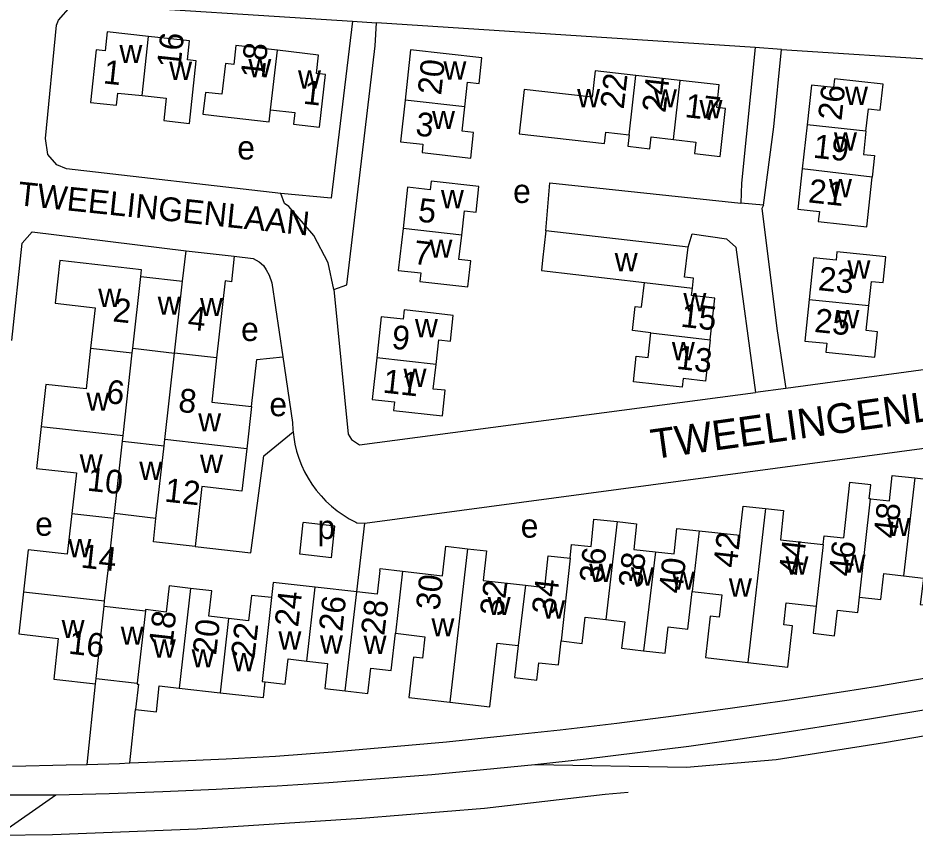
# Model space of a CAD drawing. Extents: x 161936 to 163647, y 386450 to 388633.
# Drawn here: x 162656.6 to 162807.7, y 386455.4 to 386593 of the extents above; entities that cross this region are included whole.
import ezdxf

# ---------------------------------------------------------------- set-up
doc = ezdxf.new("R2010")
doc.units = 0
for name, color, linetype in [('BLT_Basislijn', 7, 'Continuous'), ('BLT_Bebouwing', 7, 'Continuous'), ('BLT_Centroide', 7, 'Continuous'), ('BLT_Huisnummer', 7, 'Continuous'), ('BLT_Huisnummer_ tussenligend', 7, 'Continuous'), ('BLT_Huisnummer_reeks', 7, 'Continuous'), ('BLT_Onderdoorgang_en_onderverdeling', 7, 'Continuous'), ('BLT_Onderverdeling_panden', 7, 'Continuous'), ('BLT_Straatnaam', 7, 'Continuous'), ('BLT_Straatnaam_verkleind', 7, 'Continuous'), ('BLT_Vlakafsluiter', 7, 'Continuous')]:
    doc.layers.add(name, color=color, linetype=linetype)

msp = doc.modelspace()

# ---------------------------------------------------------------- linework, layer by layer
at = {"layer": 'BLT_Basislijn'}
for p, q in [((162713.01, 386592.44), (162717.03, 386592.2)), ((162780.78, 386588), (162717.03, 386592.2)), ((162785.23, 386587.71), (162780.78, 386588)), ((162782.18, 386561.46), (162778.41, 386561.84)), ((162659.05, 386557), (162684.99, 386553.82)), ((162699.39, 386548.43), (162701.24, 386535.97)), ((162701.24, 386535.97), (162702.89, 386524.91)), ((162785.97, 386530.63), (162780.83, 386529.95)), ((162704.1, 386502.73), (162704.65, 386508.03)), ((162709.43, 386502.12), (162709.99, 386507.42)), ((162713.69, 386496.39), (162715.08, 386507.97)), ((162800.38, 386475.05), (162903.47, 386492.41)), ((162668.3, 386467.34), (162669.7, 386480.91)), ((162675.51, 386467.57), (162676.46, 386476.6))]:
    msp.add_line(p, q, dxfattribs=at)
for points in [[(162700.89, 386563.47), (162664.84, 386567.62), (162663.18, 386568.3), (162661.66, 386570.04), (162661.31, 386572.71), (162663.15, 386591.79), (162663.47, 386592.62), (162665.57, 386594.96), (162667.26, 386595.36), (162713.01, 386592.44)], [(162713.01, 386592.44), (162709.37, 386562.66), (162700.89, 386563.47)], [(162709.82, 386547.31), (162712.04, 386548.09), (162716.8, 386588.3), (162717.03, 386592.2)], [(162780.78, 386588), (162778.51, 386565.16), (162778.41, 386561.84)], [(162782.18, 386561.46), (162783.92, 386574.65), (162785.23, 386587.71)], [(162785.23, 386587.71), (162841.02, 386584.11), (162844.62, 386583.54), (162846.79, 386581.59), (162847.4, 386578.61), (162842.61, 386541.25), (162842.22, 386540.22), (162841.29, 386538.99), (162838.89, 386537.8), (162785.97, 386530.63)], [(162745.56, 386557.18), (162746.19, 386565.25), (162778.41, 386561.84)], [(162709.82, 386547.31), (162708.86, 386551.75), (162706.47, 386556.37), (162702.27, 386561.24), (162701.53, 386561.74), (162700.89, 386563.47)], [(162782.18, 386561.46), (162781.94, 386560.94), (162784.48, 386540.33), (162785.97, 386530.63)], [(162655.59, 386538.71), (162657.34, 386555.09), (162659.05, 386557)], [(162769.5, 386554.43), (162770.2, 386556.64), (162775.96, 386555.82), (162777.55, 386554.39), (162780.83, 386529.95)], [(162693.07, 386552.89), (162696.28, 386552.48), (162697.29, 386551.96), (162697.98, 386551.33), (162698.47, 386550.6), (162698.93, 386549.67), (162699.39, 386548.43)], [(162709.82, 386547.31), (162712.28, 386522.91), (162712.81, 386522.01), (162714.18, 386521.12), (162780.83, 386529.95)], [(162695.96, 386527.58), (162696.89, 386535.5), (162701.24, 386535.97)], [(162715.08, 386507.97), (162847.81, 386525.76)], [(162702.89, 386524.91), (162702.94, 386523.68), (162702.98, 386523.3)], [(162686.48, 386504.04), (162695.89, 386502.94), (162698.03, 386519.27), (162702.98, 386523.3)], [(162702.98, 386523.3), (162703.08, 386522.45), (162703.29, 386521.24), (162703.58, 386520.05), (162703.95, 386518.87), (162704.4, 386517.72), (162704.92, 386516.61), (162705.51, 386515.53), (162706.16, 386514.49), (162706.89, 386513.49), (162707.68, 386512.55), (162708.52, 386511.65), (162709.43, 386510.82), (162710.39, 386510.04), (162711.39, 386509.33), (162712.44, 386508.69), (162713.53, 386508.11), (162713.71, 386508.02), (162715.08, 386507.97)], [(162709.99, 386507.42), (162704.65, 386508.03)], [(162709.43, 386502.12), (162704.1, 386502.73)], [(162801.42, 386480.49), (162886.01, 386494.96), (162889.55, 386495.55)], [(162743.7, 386467.33), (162769.26, 386466.87), (162784.31, 386468.15), (162802.58, 386471.04), (162904.51, 386488.39)], [(162699.99, 386468.74), (162709.6, 386469.47), (162719.2, 386470.27), (162728.79, 386471.16), (162738.37, 386472.12), (162747.95, 386473.17), (162757.51, 386474.29), (162767.07, 386475.49), (162776.61, 386476.78), (162786.15, 386478.14), (162795.67, 386479.58), (162801.42, 386480.49)], [(162743.7, 386467.33), (162752.35, 386468.28), (162761, 386469.32), (162769.64, 386470.43), (162778.27, 386471.62), (162786.89, 386472.9), (162795.49, 386474.25), (162800.38, 386475.05)], [(162675.51, 386467.57), (162682.72, 386467.85), (162691.71, 386468.28), (162699.99, 386468.74)], [(162655.74, 386467.05), (162664.74, 386467.24), (162668.3, 386467.34)], [(162668.3, 386467.34), (162673.73, 386467.5), (162675.51, 386467.57)], [(162700.29, 386463.75), (162708.99, 386464.31), (162717.67, 386464.94), (162726.36, 386465.66), (162735.03, 386466.45), (162743.7, 386467.33)], [(162569.36, 386464.86), (162634.81, 386462.19), (162663, 386462.19)], [(162663, 386462.19), (162672.02, 386462.44), (162681.04, 386462.78), (162690.05, 386463.18), (162699.06, 386463.68), (162700.29, 386463.75)], [(162653.28, 386455.44), (162662.47, 386455.54), (162686.82, 386456.47), (162714.52, 386458.26), (162735.24, 386459.99), (162755.52, 386462.32), (162759.42, 386462.66)]]:
    msp.add_lwpolyline(points, dxfattribs=at)
at = {"layer": 'BLT_Bebouwing'}
for p, q in [((162768.18, 386582.47), (162760.68, 386583.32)), ((162789.53, 386575.01), (162788.72, 386567.61)), ((162769.5, 386554.43), (162745.56, 386557.18)), ((162684.36, 386548.67), (162684.99, 386553.82)), ((162684.99, 386553.82), (162693.07, 386552.89)), ((162677.32, 386549.5), (162677.44, 386550.62)), ((162677.32, 386549.5), (162684.36, 386548.67)), ((162675.88, 386536.6), (162675.97, 386537.38)), ((162675.97, 386537.38), (162683.01, 386536.57)), ((162674.34, 386522.69), (162675.88, 386536.6)), ((162681.38, 386522.02), (162683.01, 386536.57)), ((162695.96, 386527.58), (162695.17, 386520.47)), ((162674.23, 386521.74), (162674.34, 386522.69)), ((162674.23, 386521.74), (162681.26, 386520.94)), ((162681.26, 386520.94), (162681.38, 386522.02)), ((162671.82, 386500), (162672.79, 386508.78)), ((162672.79, 386508.78), (162672.88, 386509.6)), ((162679.89, 386508.71), (162672.88, 386509.6)), ((162658.34, 386503.47), (162657.56, 386496.38)), ((162671.24, 386494.86), (162671.82, 386500)), ((162713.69, 386496.39), (162706.71, 386497.18)), ((162671.15, 386493.95), (162671.24, 386494.86)), ((162669.7, 386480.91), (162669.79, 386481.77)), ((162669.79, 386481.77), (162676.72, 386481)), ((162683.78, 386480.19), (162690.7, 386479.4))]:
    msp.add_line(p, q, dxfattribs=at)
for points in [[(162678.61, 386589.9), (162671.65, 386590.65), (162671.31, 386587.48), (162669.81, 386587.64), (162668.86, 386578.79), (162673.23, 386578.32), (162673.45, 386580.36), (162677.54, 386579.92)], [(162677.54, 386579.92), (162681.63, 386579.49), (162681.23, 386575.71), (162685.54, 386575.24), (162686.67, 386585.81), (162685.21, 386585.96), (162685.55, 386589.16), (162678.61, 386589.9)], [(162700.33, 386587.55), (162693.36, 386588.34), (162693, 386585.17), (162691.58, 386585.33), (162690.99, 386580.16), (162688.21, 386580.47), (162687.8, 386576.79), (162690.58, 386576.47), (162698.97, 386575.53), (162699.2, 386577.53)], [(162699.2, 386577.53), (162703.29, 386577.07), (162703.07, 386575.12), (162707.43, 386574.63), (162708.43, 386583.46), (162706.93, 386583.63), (162707.28, 386586.76), (162700.33, 386587.55)], [(162731.89, 386578.06), (162732.35, 386582.18), (162734.31, 386581.97), (162734.79, 386586.28), (162722.76, 386587.61), (162721.83, 386579.17)], [(162760.68, 386583.32), (162753.87, 386584.09), (162753.36, 386579.66), (162741.89, 386580.96), (162741.04, 386573.47), (162755.4, 386571.84), (162755.62, 386573.78), (162759.55, 386573.33)], [(162799.45, 386573.93), (162799.87, 386577.71), (162801.87, 386577.49), (162802.34, 386581.85), (162794.17, 386582.74), (162794.01, 386581.31), (162790.26, 386581.71), (162789.53, 386575.01)], [(162767.05, 386572.53), (162770.81, 386572.11), (162770.6, 386570.19), (162774.88, 386569.7), (162775.8, 386577.78), (162774.32, 386577.95), (162774.74, 386581.72), (162768.18, 386582.47)], [(162721.83, 386579.17), (162721.05, 386572.15), (162724.84, 386571.73), (162724.69, 386570.33), (162732.9, 386569.42), (162733.37, 386573.72), (162731.43, 386573.93), (162731.89, 386578.06)], [(162799.45, 386573.93), (162799.03, 386570.02), (162800.88, 386569.82), (162800.49, 386566.22)], [(162759.55, 386573.33), (162759.33, 386571.42), (162763.07, 386570.99), (162763.29, 386572.96), (162767.05, 386572.53)], [(162788.72, 386567.61), (162787.98, 386560.82), (162791.61, 386560.43), (162791.43, 386558.72), (162799.58, 386557.83), (162800.49, 386566.22)], [(162731.37, 386556.42), (162731.83, 386560.53), (162733.8, 386560.31), (162734.28, 386564.63), (162726.21, 386565.53), (162726.04, 386564.07), (162722.27, 386564.49), (162721.49, 386557.53)], [(162721.49, 386557.53), (162720.7, 386550.49), (162724.48, 386550.07), (162724.32, 386548.65), (162732.41, 386547.74), (162732.89, 386552.09), (162730.91, 386552.31), (162731.37, 386556.42)], [(162745.56, 386557.18), (162744.99, 386552.22), (162744.79, 386550.46), (162762.15, 386548.46)], [(162770.24, 386547.53), (162770.43, 386549.19), (162768.91, 386549.36), (162769.5, 386554.43)], [(162693.07, 386552.89), (162692.59, 386548.6), (162691.55, 386548.72), (162690.1, 386535.76)], [(162799.94, 386544.58), (162800.37, 386548.65), (162802.34, 386548.45), (162802.79, 386552.8), (162799.55, 386553.14), (162794.57, 386553.65), (162794.42, 386552.22), (162790.62, 386552.62), (162789.9, 386545.61)], [(162677.44, 386550.62), (162663.7, 386552.15), (162662.9, 386544.96), (162669.63, 386544.22), (162668.87, 386537.38)], [(162763.23, 386540.01), (162760.13, 386540.37), (162760.59, 386544.42), (162761.67, 386544.3), (162762.15, 386548.46)], [(162773.22, 386538.79), (162774.03, 386545.84), (162770.1, 386546.29), (162770.24, 386547.53)], [(162789.9, 386545.61), (162789.17, 386538.61), (162792.87, 386538.23), (162792.71, 386536.75), (162800.95, 386535.9), (162801.39, 386540.18), (162799.51, 386540.38), (162799.94, 386544.58)], [(162727.05, 386534.67), (162727.51, 386538.81), (162729.47, 386538.6), (162729.95, 386542.93), (162726.65, 386543.3), (162721.68, 386543.85), (162721.51, 386542.27), (162717.83, 386542.68), (162717.07, 386535.77)], [(162773.22, 386538.79), (162772.43, 386531.88), (162768.67, 386532.31), (162768.49, 386530.82), (162760.29, 386531.76), (162760.78, 386536.05), (162762.75, 386535.83), (162763.23, 386540.01)], [(162668.87, 386537.38), (162668.11, 386530.54), (162661.34, 386531.29), (162660.56, 386524.22)], [(162690.1, 386535.76), (162689.27, 386528.33), (162695.96, 386527.58)], [(162717.07, 386535.77), (162716.3, 386528.79), (162720.03, 386528.38), (162719.87, 386526.92), (162728.12, 386526.01), (162728.6, 386530.31), (162726.59, 386530.53), (162727.05, 386534.67)], [(162660.56, 386524.22), (162659.77, 386517.15), (162666.48, 386516.4), (162665.72, 386509.57)], [(162695.17, 386520.47), (162694.37, 386513.36), (162687.61, 386514.12), (162686.48, 386504.04)], [(162800.2, 386512.02), (162799.99, 386512.05), (162800.25, 386514.41), (162796.66, 386514.79), (162795.65, 386505.48)], [(162800.2, 386512.02), (162803.42, 386511.68), (162803.88, 386515.96), (162807.67, 386515.55)], [(162807.67, 386515.55), (162810.97, 386515.2), (162810.5, 386510.82), (162814.15, 386510.43)], [(162771.36, 386506.66), (162778.23, 386505.92), (162778.76, 386510.81), (162782.54, 386510.4)], [(162782.54, 386510.4), (162785.58, 386510.07), (162785.05, 386505.15), (162792.24, 386504.38)], [(162665.72, 386509.57), (162664.96, 386502.73), (162658.34, 386503.47)], [(162686.48, 386504.04), (162679.45, 386504.83), (162679.89, 386508.71)], [(162749.63, 386502.07), (162749.88, 386504.37), (162753.15, 386504.01), (162753.65, 386508.64), (162757.53, 386508.22)], [(162757.53, 386508.21), (162760.82, 386507.86), (162760.35, 386503.51), (162764.03, 386503.12)], [(162764.03, 386503.12), (162767.14, 386502.78), (162767.6, 386507.07), (162771.36, 386506.66)], [(162792.24, 386504.38), (162792.4, 386505.82), (162795.65, 386505.48)], [(162728.12, 386499.09), (162728.69, 386504.05), (162732.33, 386503.64)], [(162732.33, 386503.64), (162735.57, 386503.26), (162735, 386498.3), (162742.13, 386497.48)], [(162742.13, 386497.48), (162745.37, 386497.14), (162745.94, 386502.46), (162749.63, 386502.07)], [(162717.6, 386500), (162717.14, 386495.99), (162713.69, 386496.39)], [(162717.6, 386500), (162717.63, 386500.29), (162721.42, 386499.86)], [(162721.42, 386499.86), (162728.12, 386499.09)], [(162798.36, 386495.51), (162801.97, 386495.1), (162802.46, 386499.45), (162805.78, 386499.07)], [(162706.71, 386497.18), (162699.64, 386497.98), (162699.34, 386495.41)], [(162805.78, 386499.07), (162809.12, 386498.68), (162808.61, 386494.27), (162812.25, 386493.86)], [(162685.7, 386496.97), (162682.12, 386497.38), (162681.62, 386492.99), (162678.14, 386493.39), (162678.11, 386493.17)], [(162692.13, 386491.88), (162688.79, 386492.27), (162689.28, 386496.56), (162685.7, 386496.97)], [(162761.97, 386486.46), (162765.64, 386486.04), (162766.15, 386490.49), (162769.46, 386490.11), (162770.19, 386496.43)], [(162770.19, 386496.43), (162775.16, 386495.86), (162774.73, 386492.1), (162773.24, 386492.27), (162772.44, 386485.31), (162779.57, 386484.49)], [(162657.56, 386496.38), (162656.77, 386489.29), (162663.43, 386488.55), (162662.66, 386481.69), (162669.7, 386480.91)], [(162699.34, 386495.41), (162695.96, 386495.79), (162695.47, 386491.5), (162692.13, 386491.88)], [(162791.06, 386493.97), (162790.54, 386489.41), (162794.18, 386489), (162794.67, 386493.3), (162798.07, 386492.92), (162798.36, 386495.51)], [(162671.15, 386493.95), (162678.11, 386493.17)], [(162779.57, 386484.49), (162786.28, 386483.72), (162787.08, 386490.67), (162785.61, 386490.84), (162786.04, 386494.55), (162791.06, 386493.97)], [(162748.15, 386488.11), (162751.66, 386487.71), (162752.17, 386492.12), (162755.65, 386491.72)], [(162755.65, 386491.72), (162758.82, 386491.36), (162758.3, 386486.88), (162761.97, 386486.46)], [(162711.75, 386479.73), (162715.57, 386479.29), (162716.06, 386483.55), (162719.5, 386483.16), (162720.21, 386489.4)], [(162720.21, 386489.4), (162725.18, 386488.83), (162724.76, 386485.21), (162723.23, 386485.38), (162722.46, 386478.59), (162729.37, 386477.79)], [(162729.37, 386477.79), (162736.14, 386477.02), (162737.37, 386487.76), (162740.86, 386487.36)], [(162740.86, 386487.36), (162740.24, 386481.97), (162744, 386481.53), (162744.34, 386484.46), (162747.69, 386484.08), (162748.15, 386488.11)], [(162698.28, 386481.22), (162701.66, 386480.83), (162702.15, 386485.09), (162705.27, 386484.73)], [(162705.27, 386484.73), (162708.8, 386484.32), (162708.32, 386480.12), (162711.75, 386479.73)], [(162676.72, 386481), (162676.7, 386480.85), (162676.94, 386480.82), (162676.46, 386476.6)], [(162676.46, 386476.6), (162679.95, 386476.2), (162680.45, 386480.58), (162683.78, 386480.19)], [(162690.7, 386479.4), (162697.98, 386478.57), (162698.28, 386481.22)]]:
    msp.add_lwpolyline(points, dxfattribs=at)
at = {"layer": 'BLT_Onderdoorgang_en_onderverdeling'}
for p, q in [((162675.97, 386537.38), (162677.32, 386549.5)), ((162683.01, 386536.57), (162684.36, 386548.67)), ((162672.88, 386509.6), (162674.23, 386521.74)), ((162679.89, 386508.71), (162681.26, 386520.94)), ((162669.79, 386481.77), (162671.15, 386493.95)), ((162678.11, 386493.17), (162676.72, 386481))]:
    msp.add_line(p, q, dxfattribs=at)
at = {"layer": 'BLT_Onderverdeling_panden'}
for p, q in [((162677.54, 386579.92), (162678.61, 386589.9)), ((162699.2, 386577.53), (162700.33, 386587.55)), ((162759.55, 386573.33), (162760.68, 386583.32)), ((162767.05, 386572.53), (162768.18, 386582.47)), ((162731.89, 386578.06), (162721.83, 386579.17)), ((162799.45, 386573.93), (162789.53, 386575.01)), ((162800.49, 386566.22), (162788.72, 386567.61)), ((162731.37, 386556.42), (162721.49, 386557.53)), ((162762.15, 386548.46), (162770.24, 386547.53)), ((162789.9, 386545.61), (162799.94, 386544.58)), ((162763.23, 386540.01), (162773.22, 386538.79)), ((162668.87, 386537.38), (162675.88, 386536.6)), ((162690.1, 386535.76), (162683.01, 386536.57)), ((162727.05, 386534.67), (162717.07, 386535.77)), ((162660.56, 386524.22), (162674.34, 386522.69)), ((162695.17, 386520.47), (162681.38, 386522.02)), ((162807.67, 386515.55), (162805.78, 386499.07)), ((162798.36, 386495.51), (162800.2, 386512.02)), ((162782.54, 386510.4), (162779.57, 386484.49)), ((162665.72, 386509.57), (162672.79, 386508.78)), ((162757.53, 386508.22), (162755.65, 386491.72)), ((162771.36, 386506.66), (162770.19, 386496.43)), ((162792.24, 386504.38), (162791.06, 386493.97)), ((162732.33, 386503.64), (162729.37, 386477.79)), ((162764.03, 386503.12), (162761.97, 386486.46)), ((162749.63, 386502.07), (162748.15, 386488.11)), ((162721.42, 386499.86), (162720.21, 386489.4)), ((162685.7, 386496.97), (162683.78, 386480.19)), ((162705.27, 386484.73), (162706.71, 386497.18)), ((162742.13, 386497.48), (162740.86, 386487.36)), ((162657.56, 386496.38), (162671.24, 386494.86)), ((162711.75, 386479.73), (162713.69, 386496.39)), ((162692.13, 386491.88), (162690.7, 386479.4))]:
    msp.add_line(p, q, dxfattribs=at)
msp.add_lwpolyline([(162699.34, 386495.41), (162697.77, 386481.28), (162698.28, 386481.22)], dxfattribs=at)
at = {"layer": 'BLT_Vlakafsluiter'}
msp.add_line((162653.28, 386455.44), (162663, 386462.19), dxfattribs=at)

# ---------------------------------------------------------------- texts
at = {"layer": 'BLT_Centroide'}
for s, p in [('w', (162673.73, 386585.39)), ('w', (162682.11, 386582.58)), ('w', (162695.45, 386583.03)), ('w', (162728.3, 386582.62)), ('w', (162703.81, 386581.09)), ('w', (162750.81, 386577.97)), ('w', (162763.75, 386577.94)), ('w', (162795.92, 386578.34)), ('w', (162771.42, 386576.09)), ('w', (162726.38, 386574.28)), ('w', (162794.07, 386570.66)), ('e', (162693.58, 386569.17)), ('e', (162740.03, 386561.85)), ('w', (162793.23, 386562.81)), ('w', (162727.88, 386560.97)), ('w', (162725.95, 386552.62)), ('w', (162757.14, 386550.34)), ('w', (162796.34, 386549.12)), ('w', (162670.17, 386544.33)), ('w', (162768.71, 386543.62)), ('w', (162680.17, 386543.03)), ('w', (162687.3, 386542.8)), ('w', (162794.47, 386540.75)), ('e', (162694.22, 386538.61)), ('w', (162723.5, 386539.25)), ('w', (162766.77, 386535.38)), ('w', (162721.58, 386530.88)), ('w', (162668.18, 386526.86)), ('e', (162698.99, 386525.95)), ('w', (162687, 386523.39)), ('w', (162667.05, 386516.45)), ('w', (162687.31, 386516.38)), ('w', (162677.08, 386515.23)), ('e', (162659.54, 386505.82)), ('e', (162741.31, 386505.5)), ('w', (162803.05, 386505.77)), ('p', (162707.09, 386505.28)), ('w', (162665.13, 386502.22)), ('w', (162795.53, 386499.59)), ('w', (162752.86, 386498.03)), ('w', (162785.91, 386499.3)), ('w', (162759.88, 386497.44)), ('w', (162766.77, 386496.73)), ('w', (162776.38, 386495.56)), ('w', (162735.75, 386492.47)), ('w', (162744.92, 386491.88)), ('w', (162726.28, 386488.88)), ('w', (162664, 386488.59)), ('w', (162673.95, 386487.47)), ('w', (162700.51, 386486.66)), ('w', (162707.5, 386485.98)), ('w', (162714.85, 386485.92)), ('w', (162679.36, 386485.3)), ('w', (162685.88, 386483.66)), ('w', (162692.75, 386483.01))]:
    msp.add_text(s, height=4, dxfattribs=at).set_placement(p)
at = {"layer": 'BLT_Huisnummer'}
for s, rotation, p in [('16', 83.8872, (162684, 386584.41)), ('18', 83.5588, (162698.09, 386582.69)), ('1', 353.8873, (162670.9, 386582)), ('20', 83.6728, (162727.9, 386579.9)), ('22', 83.5207, (162758.65, 386577.55)), ('24', 83.5155, (162765.69, 386576.93)), ('1', 353.5603, (162704.57, 386578.58)), ('26', 83.8011, (162795.33, 386575.62)), ('17', 353.5028, (162768.83, 386576.32)), ('3', 353.6751, (162723.49, 386573.23)), ('19', 353.7932, (162790.45, 386569.49)), ('21', 353.7889, (162789.63, 386561.97)), ('5', 353.6108, (162723.89, 386558.74)), ('7', 353.6194, (162723.12, 386551.61)), ('23', 354.102, (162791.29, 386547.19)), ('15', 353.4398, (162768.14, 386541.04)), ('25', 354.0979, (162790.66, 386540.15)), ('9', 353.7001, (162719.45, 386537.36)), ('13', 353.4422, (162767.41, 386533.94)), ('11', 353.6956, (162717.98, 386529.94)), ('6', 353.6566, (162671.39, 386528.18)), ('8', 353.6108, (162683.53, 386526.72)), ('42', 83.4655, (162777.69, 386500.32)), ('14', 353.6598, (162667.12, 386500.49)), ('46', 83.6454, (162797.13, 386498.86)), ('38', 83.47, (162761.71, 386496.91)), ('30', 83.9216, (162727.62, 386493.18)), ('34', 83.47, (162747.12, 386492.42)), ('26', 83.4717, (162711.26, 386489.58)), ('22', 83.4629, (162696.46, 386485.04))]:
    msp.add_text(s, height=4, rotation=rotation, dxfattribs=at).set_placement(p)
at = {"layer": 'BLT_Huisnummer_ tussenligend'}
for s, rotation, p in [('48', 83.4676, (162804.66, 386505.26)), ('44', 83.5555, (162788.71, 386499.01)), ('36', 83.9216, (162755.14, 386497.76)), ('40', 83.4658, (162768.5, 386495.99)), ('32', 82.8413, (162738.36, 386492.16)), ('24', 83.4703, (162703.82, 386490.36)), ('28', 82.8413, (162718.32, 386488.92)), ('20', 83.4684, (162690.01, 386485.64))]:
    msp.add_text(s, height=4, rotation=rotation, dxfattribs=at).set_placement(p)
at = {"layer": 'BLT_Huisnummer_reeks'}
for s, rotation, p in [('2', 353.6625, (162672.5, 386541.93)), ('4', 353.4895, (162685.1, 386540.59)), ('10', 353.6634, (162668.18, 386513.44)), ('12', 353.6115, (162681.2, 386511.6)), ('18', 83.4698, (162682.65, 386487.06)), ('16', 353.6616, (162665.04, 386485.98))]:
    msp.add_text(s, height=4, rotation=rotation, dxfattribs=at).set_placement(p)
at = {"layer": 'BLT_Straatnaam'}
msp.add_text('TWEELINGENLAAN', height=5, rotation=7.8784, dxfattribs=at).set_placement((162763.58, 386518.72))
at = {"layer": 'BLT_Straatnaam_verkleind'}
msp.add_text('TWEELINGENLAAN', height=4, rotation=354.0296, dxfattribs=at).set_placement((162656.47, 386561.49))

doc.saveas('drawing.dxf')
